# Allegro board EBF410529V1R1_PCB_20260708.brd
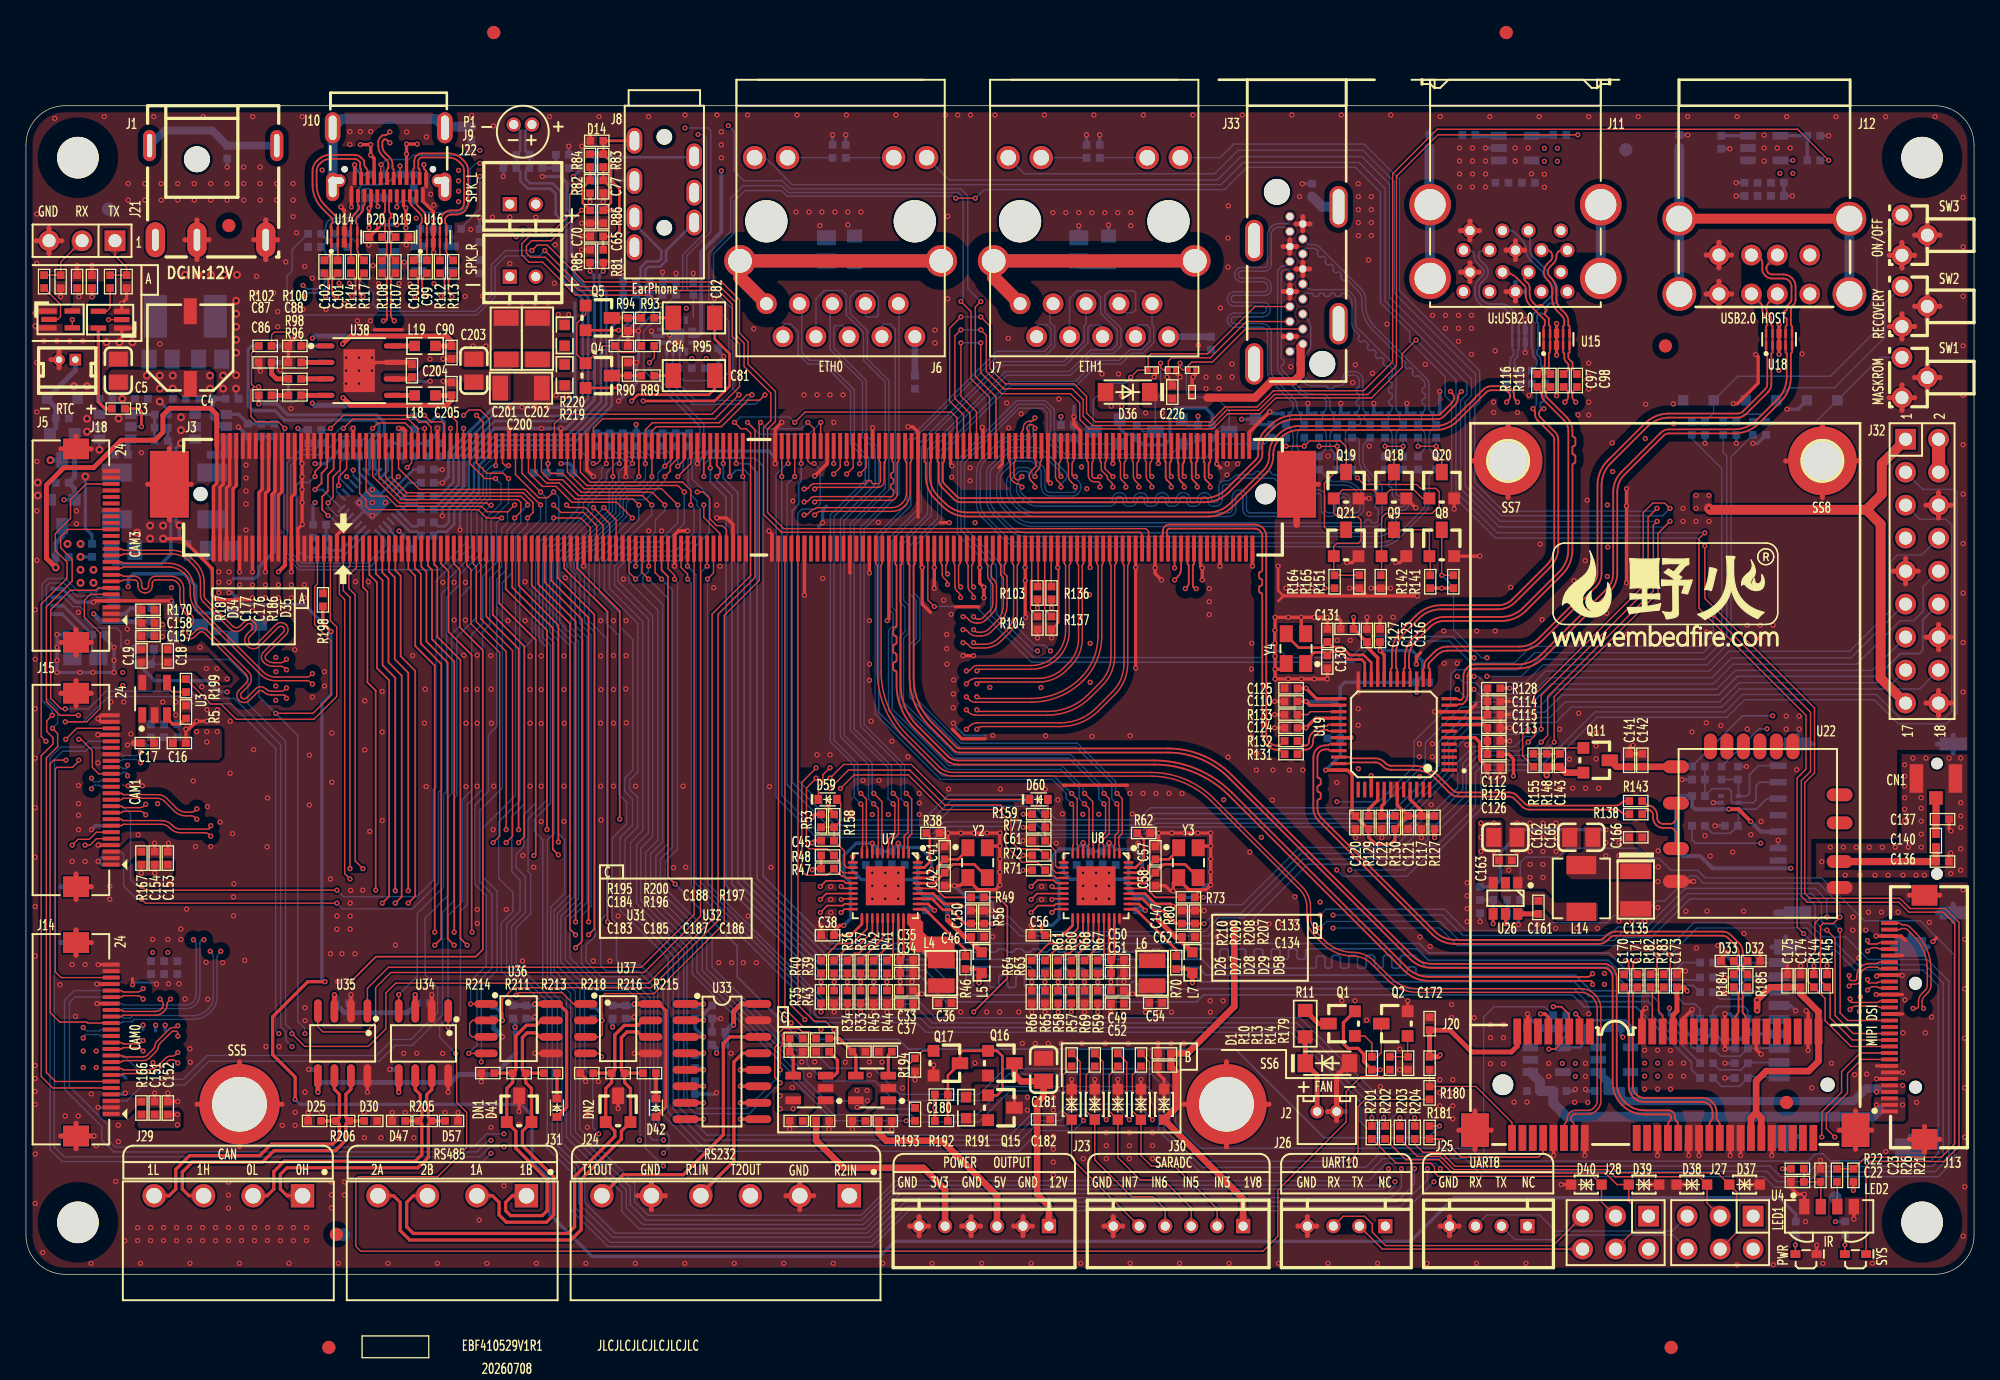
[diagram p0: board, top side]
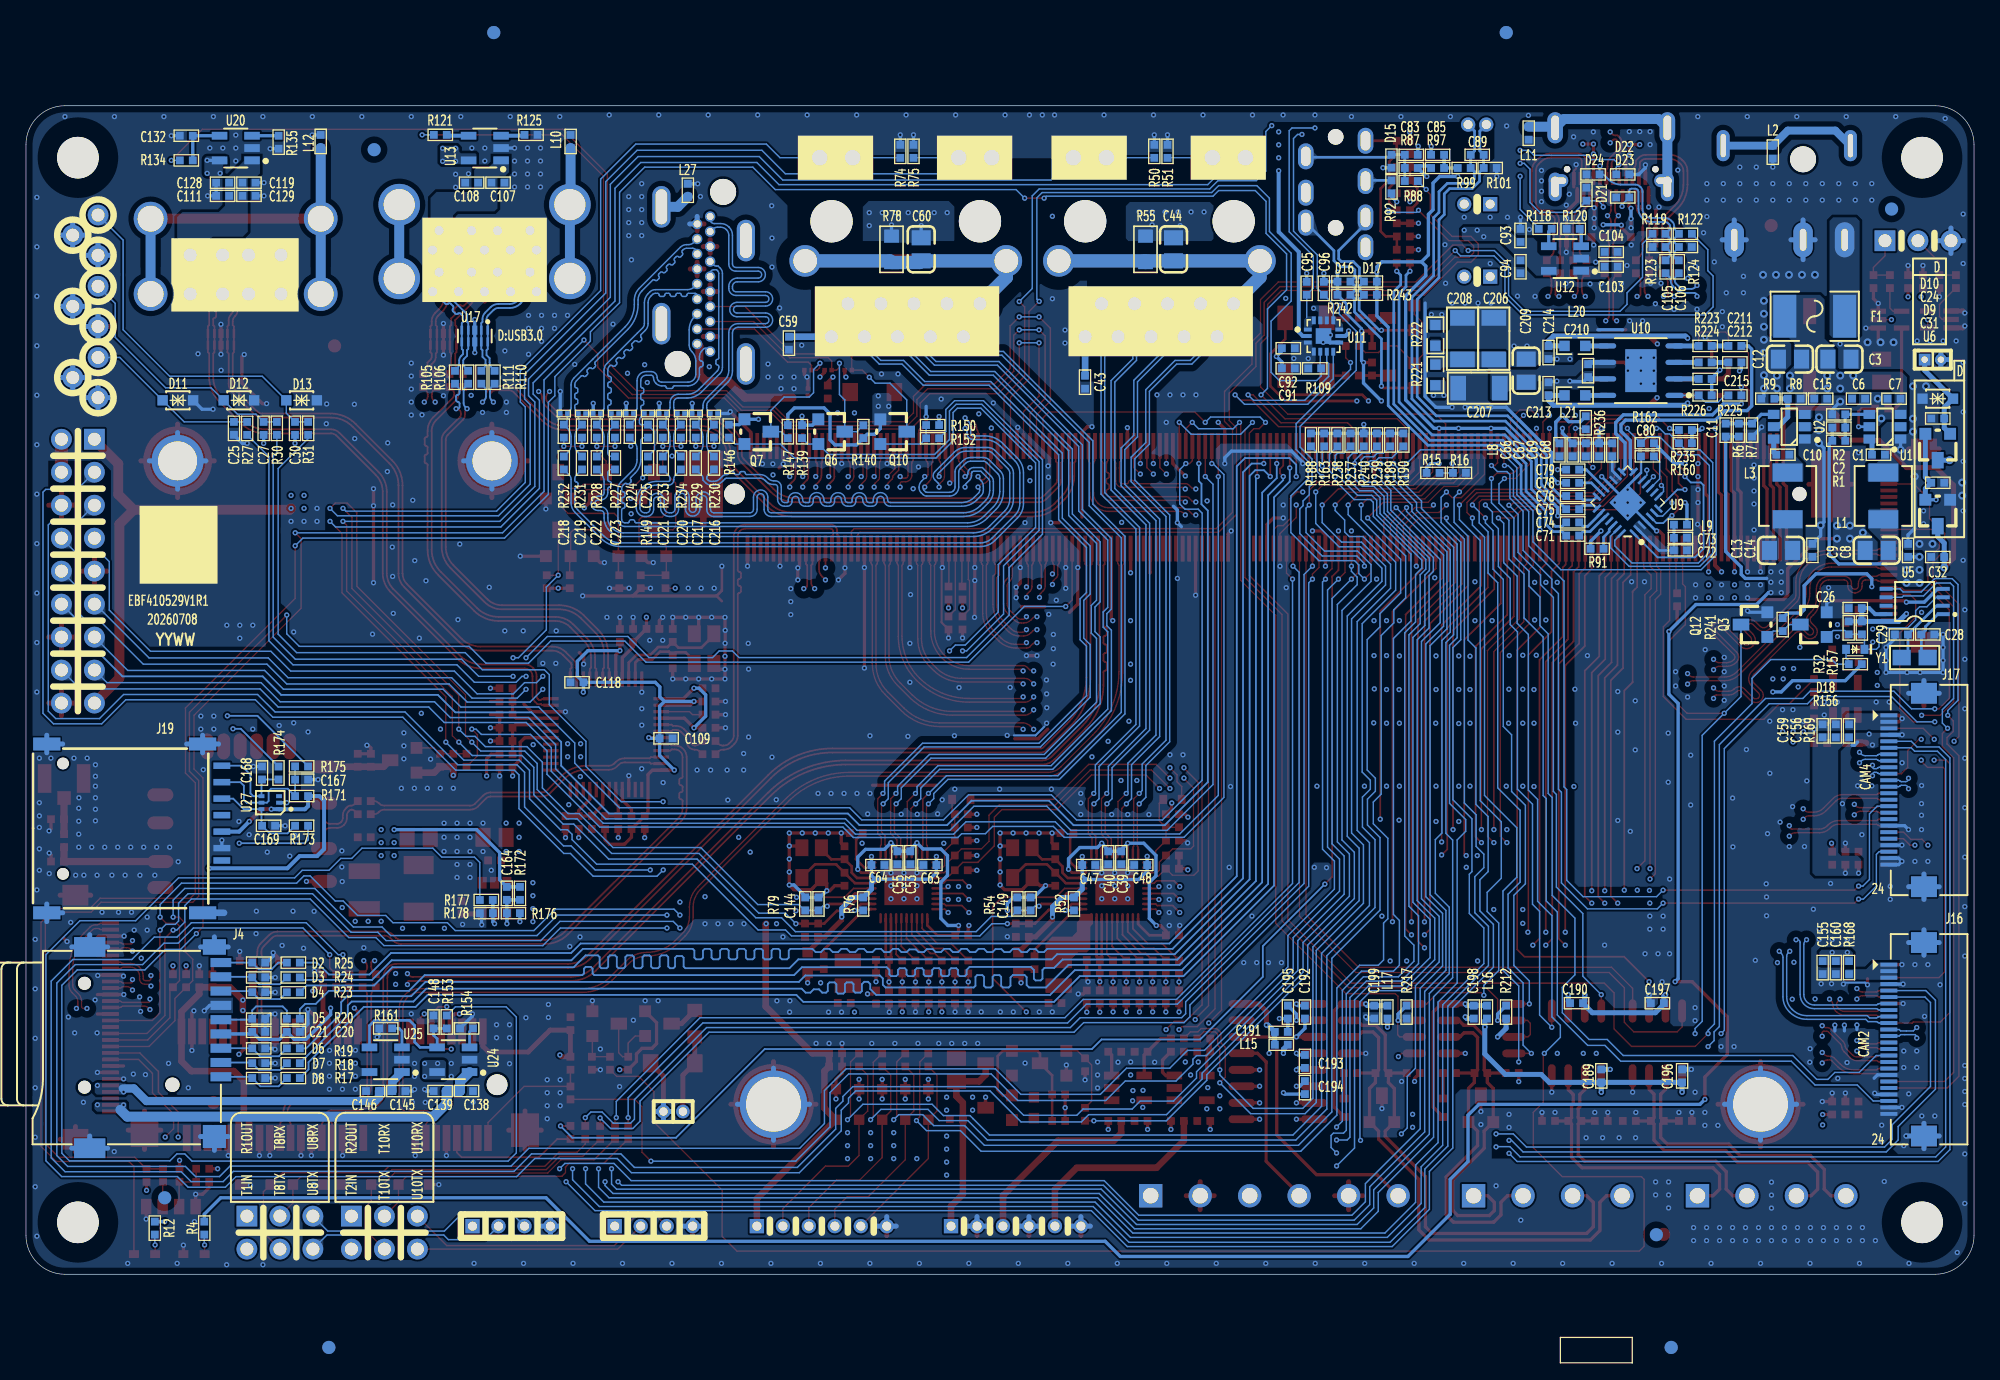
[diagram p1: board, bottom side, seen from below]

Outline 150 x 90 mm; copper layers: TOP, GND02, ART03, PWR04, GND05, BOTTOM. Coordinates in mm from the lower left corner of the outline.
Outline path: 0,87 arc(0.88,89.12) 3,90 147,90 arc(149.12,89.12) 150,87 150,3 arc(149.12,0.88) 147,0 3,0 arc(0.88,0.88) 0,3 0,87

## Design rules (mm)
constraint set DEFAULT: min track width 0.107
net group DIFFPAIR11: nets N17064495 N17064497
net group DIFFPAIR12: nets USB_HUB_DM3 USB_HUB_DP3
net group DIFFPAIR13: nets USB_HUB_DM4 USB_HUB_DP4
net group DIFFPAIR29: nets PCIE0_RXN PCIE0_RXP
net group DIFFPAIR30: nets PCIE0_REFCLKN PCIE0_REFCLKP
net group DP_TX_AUXN: nets DP_TX_AUXN SUB2
net group DP_TX_AUXP: nets DP_TX_AUXP SUB1
net group ETH0_MCLK_M0: nets ETH0_MCLK_M0 N16970797
net group ETH1_MCLK_M0: nets ETH1_MCLK_M0 N16976515
net group HDMI_TX_D0N: nets HDMI_TX_D0N HDMI_TX_D0N_PORT
net group HDMI_TX_D0P: nets HDMI_TX_D0P HDMI_TX_D0P_PORT
net group HDMI_TX_D1N: nets HDMI_TX_D1N HDMI_TX_D1N_PORT
net group HDMI_TX_D1P: nets HDMI_TX_D1P HDMI_TX_D1P_PORT
net group HDMI_TX_D2N: nets HDMI_TX_D2N HDMI_TX_D2N_PORT
net group HDMI_TX_D2P: nets HDMI_TX_D2P HDMI_TX_D2P_PORT
net group HDMI_TX_D3N: nets HDMI_TX_D3N HDMI_TX_D3N_PORT
net group HDMI_TX_D3P: nets HDMI_TX_D3P HDMI_TX_D3P_PORT
net group HDMI_TX_EARC+: nets HDMI_TX_EARC+ HDMI_TX_SBDP
net group HDMI_TX_EARC-: nets HDMI_TX_EARC- HDMI_TX_SBDN
net group MINIPCIE_NWDISABLE: nets MINIPCIE_NWDISABLE N17046548
net group PCIE0_CLKREQN_M0: nets N17044212 PCIE0_CLKREQN_M0
net group PCIE0_PERSTN: nets N17046561 PCIE0_PERSTN
net group PCIE0_TXN: nets PCIE0_TXN PE_TXN
net group PCIE0_TXP: nets PCIE0_TXP PE_TXP
net group PCIE0_WAKEN_M0: nets N17043933 PCIE0_WAKEN_M0
net group PWM0_CH0_M0_IR: nets N16966392 PWM0_CH0_M0_IR
net group SDMMC0_DETN: nets N16965221 SDMMC0_DETN
net group SIM_CLK0: nets N17036090 SIM_CLK0
net group SIM_DATA0: nets N17036093 SIM_DATA0
net group SIM_RST0: nets N17036087 SIM_RST0
net group TYPEC_SSRXN1: nets TYPEC_SSRXN1 USB3_OTG0_SSRX1N
net group TYPEC_SSRXN2: nets TYPEC_SSRXN2 USB3_OTG0_SSRX2N
net group TYPEC_SSRXP1: nets TYPEC_SSRXP1 USB3_OTG0_SSRX1P
net group TYPEC_SSRXP2: nets TYPEC_SSRXP2 USB3_OTG0_SSRX2P
net group TYPEC_SSTXN1: nets TYPEC_SSTXN1 USB3_OTG0_SSTX1N
net group TYPEC_SSTXN2: nets TYPEC_SSTXN2 USB3_OTG0_SSTX2N
net group TYPEC_SSTXP1: nets TYPEC_SSTXP1 USB3_OTG0_SSTX1P
net group TYPEC_SSTXP2: nets TYPEC_SSTXP2 USB3_OTG0_SSTX2P
net group USB2_OTG1_DM: nets N17161102 USB2_OTG1_DM
net group USB2_OTG1_DP: nets N17161099 USB2_OTG1_DP
net group USB20_DM2: nets USB20_DM2 USB_HUB_DM2
net group USB20_DP2: nets USB20_DP2 USB_HUB_DP2
net group USB30_DM: nets USB30_DM USB_HUB_DM1
net group USB30_DP: nets USB30_DP USB_HUB_DP1
net group USB30_RXN: nets USB3_OTG1_SSRXN USB30_RXN
net group USB30_RXP: nets USB3_OTG1_SSRXP USB30_RXP
net group USB30_TXN: nets USB3_OTG1_SSTXN USB30_TXN
net group USB30_TXP: nets USB3_OTG1_SSTXP USB30_TXP
net group USB_HUB_DM5: nets N17046088 USB_HUB_DM5
net group USB_HUB_DM6: nets N17367190 USB_HUB_DM6
net group USB_HUB_DP5: nets N17046085 USB_HUB_DP5
net group USB_HUB_DP6: nets N17367118 USB_HUB_DP6
net group 3W: nets CTP_RST LCD_BL_PWM LCD_RST
net group 50OHM: nets SAI1_LRCK_M0 SAI1_MCLK_M0 SAI1_SCLK_M0 SPI1_CLK_M0
net group C_GND_P: nets N16958730 N16985416 N17150434 N17163205 N17318769
net group PWR: nets 3V3_WLAN 12V_OUT RMII0_AVDD33 RMII1_AVDD33 RS485_1_3V3 RS485_2_3V3 SIM_VDD VCC3V3_RTC_S5 VCC_RTC
net group TYPEC_DM: nets USB2_OTG0_DM
net group TYPEC_DP: nets USB2_OTG0_DP

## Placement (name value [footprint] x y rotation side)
C1  0.1uF  [C0402]  7.36 63.12 180 bottom
C2  NC  [C0402]  10.41 65.21 0 bottom
C3  22uF  [C0805]  10.36 70.48 180 bottom
C4  100uF  [EC6P3]  12.65 71.37 180 top
C5  22uF  [C0805]  7.11 69.6 90 top
C6  0.1uF  [C0402]  8.89 67.44 180 bottom
C7  0.1uF  [C0402]  6.16 67.43 0 bottom
C8  0.1uF  [C0402]  5.08 55.75 90 bottom
C9  22uF  [C0805]  7.49 55.75 0 bottom
C10  0.1uF  [C0402]  14.72 63.12 180 bottom
C11  NC  [C0402]  19.12 65.02 270 bottom
C12  22uF  [C0805]  14.17 70.48 0 bottom
C13  22uF  [C0805]  14.86 55.75 0 bottom
C14  0.1uF  [C0402]  12.45 55.75 90 bottom
C15  0.1uF  [C0402]  11.81 67.44 180 bottom
C16  10uF  [C0402]  11.81 40.91 0 top
C17  0.1uF  [C0402]  9.35 40.91 180 top
C18  10uF  [C0402]  10.92 47.62 90 top
C19  0.1uF  [C0402]  8.89 47.62 90 top
C20  10uF  [C0402]  129.41 18.67 180 bottom
C21  0.1uF  [C0402]  132.08 18.67 180 bottom
C22  10uF  [C0402]  136.4 7.11 180 top
C23  0.1uF  [C0402]  138.18 7.62 90 top
C24  10uF  [C0402]  2.79 65.91 0 bottom
C25  NC  [C0402]  133.99 65.15 270 bottom
C26  0.1uF  [C0402]  9.14 51.31 0 bottom
C27  NC  [C0402]  131.7 65.15 270 bottom
C28  18pF  [C0402]  3.56 49.28 180 bottom
C29  18pF  [C0402]  5.59 49.28 0 bottom
C30  0.1uF  [C0402]  129.29 65.15 270 bottom
C31  1uF  [C0402]  2.79 60.96 180 bottom
C32  1uF  [C0402]  2.79 55.24 0 bottom
C33  10uF  [C0402]  67.82 21.86 0 top
C34  0.1uF  [C0402]  67.82 23.19 0 top
C35  0.1uF  [C0402]  67.82 24.21 0 top
C36  10uF  [C0402]  70.76 20.89 0 top
C37  0.1uF  [C0402]  67.82 20.85 180 top
C38  0.1uF  [C0402]  61.72 26.11 180 top
C39  0.1uF  [C0402]  65.67 32.08 270 bottom
C40  0.1uF  [C0402]  66.67 32.08 270 bottom
C41  18pF  [C0402]  70.74 32.46 90 top
C42  18pF  [C0402]  70.74 30.43 270 top
C43  0.1uF  [C0402]  68.45 68.71 270 bottom
C44  1nF  [C0805]  61.64 78.94 90 bottom
C45  0.1uF  [C0402]  61.72 33.4 180 top
C46  10uF  [C0402]  73.28 25.98 0 top
C47  0.1uF  [C0402]  68.17 31.52 180 bottom
C48  0.1uF  [C0402]  64.17 31.52 0 bottom
C49  10uF  [C0402]  84.05 21.86 0 top
C50  0.1uF  [C0402]  84.05 24.21 0 top
C51  0.1uF  [C0402]  84.05 23.19 0 top
C52  10uF  [C0402]  84.05 20.85 180 top
C53  0.1uF  [C0402]  81.91 32.08 270 bottom
C54  0.1uF  [C0402]  87 20.9 0 top
C55  0.1uF  [C0402]  82.9 32.08 270 bottom
C56  0.1uF  [C0402]  77.95 26.11 180 top
C57  18pF  [C0402]  86.97 32.46 90 top
C58  18pF  [C0402]  86.97 30.43 270 top
C59  0.1uF  [C0402]  91.25 71.71 270 bottom
C60  1nF  [C0805]  81.07 78.94 90 bottom
C61  0.1uF  [C0402]  77.98 33.4 180 top
C62  10uF  [C0402]  89.51 25.98 0 top
C63  0.1uF  [C0402]  80.4 31.52 0 bottom
C64  0.1uF  [C0402]  84.4 31.52 180 bottom
C65  270pF  [C0402]  43.94 79.93 180 top
C66  0.1uF  [C0402]  30.91 63.5 90 bottom
C67  0.1uF  [C0402]  29.89 63.5 90 bottom
C68  10uF  [C0402]  27.86 63.5 90 bottom
C69  10uF  [C0402]  28.87 63.5 90 bottom
C70  10uF  [C0402]  43.43 81.45 270 top
C71  1uF  [C0402]  30.91 56.89 0 bottom
C72  0.1uF  [C0402]  22.61 55.75 180 bottom
C73  10uF  [C0402]  22.61 56.72 180 bottom
C74  1uF  [C0402]  30.91 57.91 0 bottom
C75  1uF  [C0402]  30.91 58.93 0 bottom
C76  1uF  [C0402]  30.91 59.94 0 bottom
C77  NC  [C0402]  44.45 83.76 270 top
C78  10uF  [C0402]  30.91 60.96 0 bottom
C79  10uF  [C0402]  30.91 61.97 0 bottom
C80  10uF  [C0402]  25.15 62.99 0 bottom
C81  47uF  [C1206]  51.44 69.22 0 top
C82  47uF  [C1206]  51.44 73.66 0 top
C83  0.1uF  [C0402]  43.33 86.22 180 bottom
C84  0.1uF  [C0402]  45.85 71.5 0 top
C85  10uF  [C0402]  41.3 86.22 0 bottom
C86  0.1uF  [C0402]  18.41 67.69 0 top
C87  0.1uF  [C0402]  18.41 70.23 0 top
C88  1uF  [C0402]  20.7 70.23 180 top
C89  100pF  [C0402]  38.26 86.22 180 bottom
C90  1nF  [C0402]  32.77 70.99 270 top
C91  0.1uF  [C0402]  52.8 69.78 0 bottom
C92  10uF  [C0402]  52.8 71.32 0 bottom
C93  10uF  [C0402]  34.92 80.01 90 bottom
C94  0.1uF  [C0402]  34.92 77.6 270 bottom
C95  220pF  [C0402]  51.38 75.94 90 bottom
C96  220pF  [C0402]  50.06 75.94 90 bottom
C97  0.1uF  [C0402]  118.4 68.83 270 top
C98  0.1uF  [C0402]  119.42 68.83 270 top
C99  0.1uF  [C0402]  30.86 77.6 270 top
C100  0.1uF  [C0402]  29.84 77.6 270 top
C101  0.1uF  [C0402]  24 77.6 270 top
C102  0.1uF  [C0402]  22.99 77.6 270 top
C103  10uF  [C0402]  27.94 77.6 180 bottom
C104  0.1uF  [C0402]  27.94 78.74 180 bottom
C105  0.1uF  [C0402]  23.75 77.6 270 bottom
C106  0.1uF  [C0402]  22.73 77.6 270 bottom
C107  10uF  [C0402]  113.65 84.07 180 bottom
C108  0.1uF  [C0402]  115.68 84.07 0 bottom
C109  0.1uF  [C0402]  100.71 41.27 180 bottom
C110  0.1uF  [C0402]  97.41 44.12 180 top
C111  10uF  [C0402]  134.86 83.06 0 bottom
C112  NC  [C0402]  113.03 41.07 0 top
C113  NC  [C0402]  113.03 42.09 0 top
C114  NC  [C0402]  113.03 44.12 0 top
C115  NC  [C0402]  113.03 43.1 0 top
C116  0.1uF  [C0402]  104.27 49.2 90 top
C117  0.1uF  [C0402]  107.44 34.8 270 top
C118  0.1uF  [C0402]  107.57 45.59 0 bottom
C119  10uF  [C0402]  132.83 84.07 180 bottom
C120  0.1uF  [C0402]  102.36 34.8 270 top
C121  0.1uF  [C0402]  106.43 34.8 270 top
C122  0.1uF  [C0402]  104.39 34.8 270 top
C123  10uF  [C0402]  103.25 49.2 90 top
C124  0.1uF  [C0402]  97.41 42.09 180 top
C125  0.1uF  [C0402]  97.41 45.14 180 top
C126  0.1uF  [C0402]  113.03 39.04 0 top
C127  0.1uF  [C0402]  101.73 49.71 180 top
C128  10uF  [C0402]  134.86 84.07 0 bottom
C129  0.1uF  [C0402]  132.83 83.06 180 bottom
C130  NC  [C0402]  100.2 47.17 270 top
C131  NC  [C0402]  100.2 49.2 90 top
C132  0.1uF  [C0402]  137.65 87.69 0 bottom
C133  10uF  [C0402]  87.66 17.02 180 top
C134  0.1uF  [C0402]  87.66 16 180 top
C135  220uF  [CASE-B_3528]  123.95 29.59 270 top
C136  NC  [C0402]  147.57 31.79 0 top
C137  NC  [C0402]  147.57 35.05 0 top
C138  10uF  [C0402]  116.08 14.11 180 bottom
C139  0.1uF  [C0402]  118.11 14.11 0 bottom
C140  10pF  [C0402]  147.07 33.4 90 top
C141  10uF  [C0402]  123.44 39.59 90 top
C142  0.1uF  [C0402]  124.46 39.59 90 top
C143  0.1uF  [C0402]  118.11 39.59 90 top
C144  100pF  [C0402]  88.98 28.52 90 bottom
C145  10uF  [C0402]  121.28 14.11 180 bottom
C146  0.1uF  [C0402]  123.32 14.11 0 bottom
C147  100pF  [C0402]  89 27.51 90 top
C148  0.1uF  [C0402]  118.62 19.43 90 bottom
C149  100pF  [C0402]  72.64 28.52 90 bottom
C150  100pF  [C0402]  72.77 27.51 90 top
C151  10uF  [C0402]  9.91 12.8 90 top
C152  0.1uF  [C0402]  10.92 12.8 90 top
C153  10uF  [C0402]  10.92 32.05 90 top
C154  0.1uF  [C0402]  9.91 32.05 90 top
C155  10uF  [C0402]  11.66 23.62 270 bottom
C156  0.1uF  [C0402]  10.64 41.85 90 bottom
C157  10uF  [C0402]  9.4 49.15 180 top
C158  0.1uF  [C0402]  9.4 50.16 180 top
C159  10uF  [C0402]  11.66 41.85 90 bottom
C160  0.1uF  [C0402]  10.64 23.62 270 bottom
C161  0.1uF  [C0402]  116.46 28.26 90 top
C162  22uF  [C0805]  113.92 33.66 0 top
C163  0.1uF  [C0402]  113.92 31.88 0 top
C164  NC  [C0402]  112.98 29.34 90 bottom
C165  22uF  [C0805]  119.76 33.66 180 top
C166  0.1uF  [C0402]  123.95 33.66 0 top
C167  33pF  [C0402]  128.78 38.1 180 bottom
C168  33pF  [C0402]  131.83 38.61 90 bottom
C169  33pF  [C0402]  131.32 34.54 180 bottom
C170  0.1uF  [C0402]  123.06 22.61 270 top
C171  0.1uF  [C0402]  124.08 22.61 270 top
C172  0.1uF  [C0402]  108.08 19.3 90 top
C173  0.1uF  [C0402]  127.13 22.61 90 top
C174  0.1uF  [C0402]  136.65 22.61 90 top
C175  0.1uF  [C0402]  135.64 22.61 90 top
C176  0.1uF  [C0402]  5.08 76.45 90 top
C177  0.1uF  [C0402]  3.94 76.45 90 top
C180  0.1uF  [C0402]  70.48 13.84 0 top
C181  22uF  [C0805]  78.36 15.75 90 top
C182  0.1uF  [C0402]  78.36 11.94 0 top
C183  10uF  [C0402]  59.31 11.81 180 top
C184  0.1uF  [C0402]  59.31 17.14 0 top
C185  0.1uF  [C0402]  61.34 11.81 0 top
C186  10uF  [C0402]  66.17 11.81 0 top
C187  0.1uF  [C0402]  64.14 11.81 180 top
C188  0.1uF  [C0402]  64.14 17.14 0 top
C189  0.1uF  [C0402]  28.7 15.28 90 bottom
C190  0.1uF  [C0402]  30.61 20.88 0 bottom
C191  0.1uF  [C0402]  53.34 18.67 180 bottom
C192  0.1uF  [C0402]  51.52 20.19 90 bottom
C193  0.1uF  [C0402]  51.52 16.39 90 bottom
C194  0.1uF  [C0402]  51.52 14.38 270 bottom
C195  0.1uF  [C0402]  52.83 20.19 270 bottom
C196  0.1uF  [C0402]  22.48 15.28 90 bottom
C197  0.1uF  [C0402]  24.38 20.88 0 bottom
C198  0.1uF  [C0402]  38.52 20.19 270 bottom
C199  0.1uF  [C0402]  46.18 20.19 270 bottom
C200  47uF  [C1206]  38.12 68.25 0 top
C201  47uF  [C1206]  36.98 72.06 90 top
C202  47uF  [C1206]  39.39 72.06 90 top
C203  22uF  [C0805]  34.49 69.6 90 top
C204  0.1uF  [C0402]  29.72 69.6 90 top
C205  1nF  [C0402]  32.77 68.2 90 top
C206  47uF  [C1206]  36.98 72.06 90 bottom
C207  47uF  [C1206]  38.12 68.25 0 bottom
C208  47uF  [C1206]  39.39 72.06 90 bottom
C209  22uF  [C0805]  34.49 69.6 90 bottom
C210  0.1uF  [C0402]  29.72 69.6 270 bottom
C211  0.1uF  [C0402]  18.41 71.5 0 bottom
C212  0.1uF  [C0402]  18.41 70.23 0 bottom
C213  1nF  [C0402]  32.77 68.2 90 bottom
C214  1nF  [C0402]  32.77 70.99 270 bottom
C215  1uF  [C0402]  20.7 68.96 180 bottom
C216  0.22uF  [C0402]  97.03 62.48 90 bottom
C217  0.22uF  [C0402]  98.42 62.48 90 bottom
C218  0.22uF  [C0402]  108.58 62.48 90 bottom
C219  0.22uF  [C0402]  107.19 62.48 90 bottom
C220  0.22uF  [C0402]  99.57 62.48 90 bottom
C221  0.22uF  [C0402]  100.97 62.48 90 bottom
C222  0.22uF  [C0402]  106.05 62.48 90 bottom
C223  0.22uF  [C0402]  104.65 62.48 90 bottom
C224  1uF  [C0402]  103.5 64.94 90 bottom
C225  1uF  [C0402]  102.11 64.94 90 bottom
C226  1uF  [C0402]  88.27 67.94 90 top
CN1  WiFi-Ant  [UFL-3]  147.07 38.18 0 top
D1  1N4148W  [SOD-123]  100.2 16.26 180 top
D2  KLXES15AAA1  [ES0402]  132.08 24 0 bottom
D3  KLXES15AAA1  [ES0402]  132.08 22.86 0 bottom
D4  KLXES15AAA1  [ES0402]  132.08 21.72 0 bottom
D5  KLXES15AAA1  [ES0402]  132.08 19.68 0 bottom
D6  KLXES15AAA1  [ES0402]  132.08 17.4 0 bottom
D7  KLXES15AAA1  [ES0402]  132.08 16.26 0 bottom
D8  KLXES15AAA1  [ES0402]  132.08 15.11 0 bottom
D9  BAT54C  [SOT23]  2.79 63.74 0 bottom
D10  PESD3V3L1BA  [SOD323_T]  2.79 67.44 180 bottom
D11  PESD3V3L1BA  [SOD323_T]  138.3 67.31 0 bottom
D12  PESD3V3L1BA  [SOD323_T]  133.6 67.31 0 bottom
D13  PESD3V3L1BA  [SOD323_T]  128.78 67.31 0 bottom
D14  D2315-5R0B  [ESD0402]  43.95 87.3 0 top
D15  D2315-5R0B  [ESD0402]  44.86 85.72 90 bottom
D16  D2315-5R0B  [ESD0402]  48.51 76.45 180 bottom
D17  D2315-5R0B  [ESD0402]  46.48 76.45 0 bottom
D18  B5819WT  [SOD523]  9.14 48.13 0 bottom
D19  KLXES15AAA1  [ES0402]  28.96 79.88 180 top
D20  KLXES15AAA1  [ES0402]  26.92 79.88 0 top
D21  KLXES15AAA1  [ES0402]  29.84 83.19 270 bottom
D22  KLXES15AAA1  [ES0402]  27.05 84.71 0 bottom
D23  KLXES15AAA1  [ES0402]  27.05 82.93 180 bottom
D24  KLXES15AAA1  [ES0402]  29.34 84.71 180 bottom
D25  D2315-5R0B  [ESD0402]  22.23 11.81 180 top
D26  PESD3V3L1BA  [SOD323_T]  80.52 13.08 270 top
D27  PESD3V3L1BA  [SOD323_T]  82.3 13.08 270 top
D28  PESD3V3L1BA  [SOD323_T]  84.07 13.08 270 top
D29  PESD3V3L1BA  [SOD323_T]  85.85 13.08 270 top
D30  D2315-5R0B  [ESD0402]  26.54 11.81 0 top
D31  TPESD0201G05V  [R0201]  102.11 66.29 0 bottom
D32  KLXES15AAA1  [ES0402]  133.05 24.13 0 top
D33  KLXES15AAA1  [ES0402]  131.01 24.13 180 top
D34  D2315-3R3  [ESD0402]  2.67 76.45 90 top
D35  D2315-3R3  [ESD0402]  7.75 76.45 90 top
D36  1N5819W  [SOD-123]  84.84 67.94 0 top
D37  PESD3V3L1BA  [SOD323_T]  132.33 6.91 180 top
D38  PESD3V3L1BA  [SOD323_T]  128.27 6.91 0 top
D39  PESD3V3L1BA  [SOD323_T]  124.59 6.91 180 top
D40  PESD3V3L1BA  [SOD323_T]  120.14 6.91 0 top
D41  RB521S-30  [SOD523]  40.89 12.83 270 top
D42  RB521S-30  [SOD523]  48.51 12.83 270 top
D43  TPESD0201G05V  [R0201]  86.69 69.64 180 top
D44  TPESD0201G05V  [R0201]  103.5 66.29 180 bottom
D45  TPESD0201G05V  [R0201]  88.24 69.64 180 top
D46  TPESD0201G05V  [R0201]  89.79 69.64 180 top
D47  D2315-5R0B  [ESD0402]  28.7 11.81 180 top
D48  TPESD0201G05V  [R0201]  89.79 67.94 90 top
D49  TPESD0201G05V  [R0201]  99.57 66.29 0 bottom
D50  TPESD0201G05V  [R0201]  100.97 66.29 180 bottom
D51  TPESD0201G05V  [R0201]  106.05 66.29 180 bottom
D52  TPESD0201G05V  [R0201]  104.65 66.29 0 bottom
D53  TPESD0201G05V  [R0201]  97.03 66.29 0 bottom
D54  TPESD0201G05V  [R0201]  98.42 66.29 180 bottom
D55  TPESD0201G05V  [R0201]  108.58 66.29 180 bottom
D56  TPESD0201G05V  [R0201]  107.19 66.29 0 bottom
D57  D2315-5R0B  [ESD0402]  32.77 11.81 0 top
D58  PESD3V3L1BA  [SOD323_T]  87.63 13.08 270 top
D59  RB521S-30  [SOD523]  61.72 36.58 0 top
D60  RB521S-30  [SOD523]  77.98 36.58 0 top
DN1  SM712  [SOT23]  37.97 12.71 0 top
DN2  SM712  [SOT23]  45.59 12.71 0 top
F1  SMD1812P200TF16  [F1812]  12.27 73.79 0 bottom
J1  DC-044A-20A  [DC_IN_TH_3P_10R1X11R6]  14.41 84.18 270 top
J2  A1501WV-2P  [ZH1P5MM_TH_2P]  100.17 12.53 0 top
J3  -  [AS0B821-S55B-7H]  54.44 59.85 0 top
J4  TF_Card  [TFCARD]  145.49 18.41 270 bottom
J5  1.25T-2A  [GH1P25_TH_2P]  3.18 70.45 180 top
J6  -  [HY911130A]  62.73 81.1 0 top
J7  -  [HY911130A]  82.26 81.1 0 top
J8  PJ-393-7P  [AV7_6X14R50_TM]  49.15 84.1 0 top
J9  PH-2A  [PH-1X2-2P0_L]  38.26 82.42 0 top
J10  TYPE-C  [USB-C-SMD_TYC-324G]  27.93 85.68 180 top
J11  USB3D0_USB2D0-A-D  [USB3D0-AF-18P]  114.69 78.88 180 top
J12  -  [USB-A-D]  133.86 82 0 top
J13  FPC_0R5_30P_D  [FPC-30P-0P5]  144.84 19.8 90 top
J14  FPC_0P5_24P_D  [FPC_24P_0P5]  5.21 18.1 90 top
J15  FPC_0P5_24P_D  [FPC_24P_0P5]  5.21 37.3 90 top
J16  FPC_0P5_24P_D  [FPC_24P_0P5]  5.21 18.1 270 bottom
J17  FPC_0P5_24P_D  [FPC_24P_0P5]  5.21 37.3 270 bottom
J18  FPC_0P5_24P_D  [FPC_24P_0P5]  5.21 56.12 90 top
J19  SIM-7-1  [NANO_SIM]  141.66 34.34 270 bottom
J20  MINI-PCIE  [PCIE_52P]  126.22 14.6 0 top
J21  -  [HDR1X3-2R54-TM-VM]  4.32 79.6 180 top
J22  PH-2A  [PH-1X2-2P0_L]  38.26 76.84 0 top
J23  PH-6A  [PH-1X6-2P0]  73.77 3.71 180 top
J24  CON6  [DB2ERC-3P81-6P]  53.87 6.05 180 top
J25  PH-4A  [PH-1X4-2P0]  112.62 3.71 180 top
J26  PH-4A  [PH-1X4-2P0]  101.67 3.71 180 top
J27  -  [HDR2X3-2R54-TM-VM]  130.45 3.21 180 top
J28  -  [HDR2X3-2R54-TM-VM]  122.4 3.21 180 top
J29  WJ15EDGRC-3.81-4P  [DB2ERC-3P81-4P]  15.58 6.05 180 top
J30  PH-6A  [PH-1X6-2P0]  88.72 3.71 180 top
J31  WJ15EDGRC-3.81-4P  [DB2ERC-3P81-4P]  32.82 6.05 180 top
J32  -  [HDR2X9-2R54-TM-VM]  146 54.15 270 top
J33  HDMI-001C  [HDMI-SMD]  97.82 76.16 90 top
L1  3.3uH  [L4520]  6.99 59.95 270 bottom
L2  120R 100MHz  [L0402]  15.49 86.43 270 bottom
L3  3.3uH  [L4520]  14.35 59.95 270 bottom
L4  2.2uH  [L2520]  70.48 23.19 270 top
L5  330R 100MHz  [L0603]  73.58 24 90 top
L6  2.2uH  [L2520]  86.72 23.19 270 top
L7  330R 100MHz  [L0603]  89.81 24 90 top
L8  120R 100MHz  [L0402]  31.92 63.5 270 bottom
L9  120R 100MHz  [L0402]  22.61 57.73 0 bottom
L10  120R 100MHz  [L0402]  108.06 87.25 90 bottom
L11  120R 100MHz  [L0402]  34.29 87.88 270 bottom
L12  120R 100MHz  [L0402]  127.31 87.25 90 bottom
L14  3.3uH  [L4520]  119.76 29.72 90 top
L15  120R 100MHz  [L0402]  53.34 17.68 180 bottom
L16  120R 100MHz  [L0402]  37.5 20.19 90 bottom
L17  120R 100MHz  [L0402]  45.17 20.19 90 bottom
L18  1K 100MHz  [L0603]  30.73 67.69 0 top
L19  1K 100MHz  [L0603]  30.73 71.5 0 top
L20  1K 100MHz  [L0603]  30.73 71.5 0 bottom
L21  1K 100MHz  [L0603]  30.73 67.69 0 bottom
L27  120R 100MHz  [L0402]  99.03 83.49 270 bottom
LED1  HS-0602-UR  [LED_HS_0602_UR]  137.06 1.56 180 top
LED2  HS-0602-UG  [LED_HS_0602_UR]  140.87 1.56 180 top
NOREF  -  []  152.54 0 0 top
NOREF#2  -  [unnamed#2]  15.62 80.77 0 top
NOREF#3  -  []  9.4 -7.62 0 top
NOREF#4  -  [unnamed#2]  135.56 13.23 0 top
NOREF#5  -  [unnamed#2]  23.9 3.07 0 top
NOREF#6  -  [unnamed#2]  126.68 -5.63 180 top
NOREF#7  -  []  154.05 56.9 0 top
NOREF#8  -  []  152.54 90 0 top
NOREF#9  -  []  208.79 7.87 0 top
NOREF#10  -  [unnamed#2]  113.98 95.64 180 top
NOREF#11  -  [unnamed#2]  36.02 95.64 0 top
NOREF#12  -  [unnamed#2]  126.24 71.5 0 top
NOREF#13  -  []  0 87 0 top
NOREF#14  -  [unnamed#2]  23.32 -5.63 0 top
NOREF#15  -  []  3 0 90 top
NOREF#16  -  [unnamed#2]  24.46 3.05 180 bottom
NOREF#17  -  [unnamed#2]  23.32 -5.63 180 bottom
NOREF#18  -  [unnamed#2]  123.19 86.61 180 bottom
NOREF#19  -  [unnamed#2]  6.35 82.04 180 bottom
NOREF#20  -  [unnamed#2]  126.68 -5.63 180 bottom
NOREF#21  -  [unnamed#2]  36.02 95.64 180 bottom
NOREF#22  -  [unnamed#2]  113.98 95.64 180 bottom
NOREF#23  -  [unnamed#2]  139.32 5.89 180 bottom
P1  MIC_POM  [MIC2-4R00-TM]  38.26 88.55 180 top
Q1  SSM3J328R-LF  [SOT23]  101.33 19.3 90 top
Q2  SS8050  [SOT23]  105.4 19.3 90 top
Q3  2SK3018  [SOT23]  12.33 50.04 90 bottom
Q4  WNM2016-3/TR  [SOT23]  44.08 69.22 270 top
Q5  WNM2016-3/TR  [SOT23]  44.08 73.66 270 top
Q6  2SK3018  [SOT23]  88 64.9 270 bottom
Q7  2SK3018  [SOT23]  93.69 64.9 270 bottom
Q8  2SK3018  [SOT23]  109.02 56.3 0 top
Q9  2SK3018  [SOT23]  105.33 56.3 0 top
Q10  2SK3018  [SOT23]  83.22 64.9 270 bottom
Q11  AO3407  [SOT23]  120.92 39.59 270 top
Q12  2SK3018  [SOT23]  16.9 50.04 90 bottom
Q15  AO3407  [SOT23]  75.07 12.83 270 top
Q16  AO3407  [SOT23]  75.07 16.26 270 top
Q17  SS8050  [SOT23]  70.88 16.26 270 top
Q18  2SK3018  [SOT23]  105.33 60.74 0 top
Q19  2SK3018  [SOT23]  101.65 60.74 0 top
Q20  2SK3018  [SOT23]  109.02 60.74 0 top
Q21  2SK3018  [SOT23]  101.65 56.3 0 top
R1  115K  [R0402]  10.41 64.2 0 bottom
R2  20K  [R0402]  10.41 66.23 0 bottom
R3  10K  [R0402]  7.11 66.67 0 top
R4  5.1K  [R0402]  136.27 3.56 270 bottom
R5  3.4K  [R0402]  12.32 43.31 90 top
R6  115K  [R0402]  18.11 65.02 270 bottom
R7  20K  [R0402]  17.09 65.02 270 bottom
R8  180K  [R0402]  13.84 67.44 180 bottom
R9  27K  [R0402]  15.88 67.44 0 bottom
R10  10K  [R0402]  103.63 16.26 90 top
R11  0R  [R0805]  98.5 19.3 270 top
R12  4.7K  [R0402]  140.08 3.56 270 bottom
R13  1K  [R0402]  105.03 16.26 90 top
R14  10K  [R0402]  106.43 16.26 270 top
R15  25.5K  [R0402]  41.66 61.72 180 bottom
R16  10K  [R0402]  39.62 61.72 180 bottom
R17  22R  [R0402]  129.41 15.11 0 bottom
R18  22R  [R0402]  129.41 16.26 0 bottom
R19  22R  [R0402]  129.41 17.4 0 bottom
R20  22R  [R0402]  129.41 19.68 0 bottom
R21  10K  [R0402]  140.72 7.62 90 top
R22  22R  [R0402]  136.4 8.13 0 top
R23  22R  [R0402]  129.41 21.72 0 bottom
R24  22R  [R0402]  129.41 22.86 0 bottom
R25  22R  [R0402]  129.41 24 0 bottom
R26  22R  [R0402]  139.45 7.62 270 top
R27  100R  [R0402]  132.97 65.15 270 bottom
R30  100R  [R0402]  130.68 65.15 270 bottom
R31  100R  [R0402]  128.27 65.15 270 bottom
R32  NC  [R0402]  9.65 49.78 270 bottom
R33  4.7K  [R0402]  64.26 21.36 90 top
R34  4.7K  [R0402]  63.25 21.36 90 top
R35  4.7K  [R0402]  61.21 21.36 90 top
R36  22R  [R0402]  63.25 23.67 90 top
R37  22R  [R0402]  64.26 23.67 90 top
R38  2.49K  [R0402]  69.84 33.99 0 top
R39  22R  [R0402]  62.23 23.67 90 top
R40  22R  [R0402]  61.21 23.67 90 top
R41  22R  [R0402]  66.29 23.67 90 top
R42  22R  [R0402]  65.28 23.67 90 top
R43  4.7K  [R0402]  62.23 21.36 270 top
R44  4.7K  [R0402]  66.29 21.36 270 top
R45  4.7K  [R0402]  65.28 21.36 270 top
R46  4.7K  [R0402]  72.34 24 90 top
R47  4.7K  [R0402]  61.72 31.24 0 top
R48  4.7K  [R0402]  61.72 32.26 0 top
R49  22R  [R0402]  73.28 29.03 180 top
R50  510R  [R0402]  63.12 86.49 90 bottom
R51  510R  [R0402]  62.1 86.49 90 bottom
R52  4.7K  [R0402]  69.3 28.52 90 bottom
R53  10K  [R0402]  61.21 34.92 270 top
R54  4.7K  [R0402]  73.66 28.52 90 bottom
R55  1M  [R0805]  63.8 78.94 90 bottom
R56  4.7K  [R0402]  73.79 27.51 90 top
R57  4.7K  [R0402]  80.49 21.36 90 top
R58  4.7K  [R0402]  79.48 21.36 90 top
R59  4.7K  [R0402]  82.52 21.36 90 top
R60  22R  [R0402]  80.49 23.67 90 top
R61  22R  [R0402]  79.48 23.67 90 top
R62  2.49K  [R0402]  86.07 33.99 0 top
R63  22R  [R0402]  78.46 23.67 90 top
R64  22R  [R0402]  77.44 23.67 90 top
R65  4.7K  [R0402]  78.46 21.36 270 top
R66  4.7K  [R0402]  77.44 21.36 270 top
R67  22R  [R0402]  82.52 23.67 90 top
R68  22R  [R0402]  81.51 23.67 90 top
R69  4.7K  [R0402]  81.51 21.36 270 top
R70  4.7K  [R0402]  88.57 24 90 top
R71  4.7K  [R0402]  77.98 31.11 0 top
R72  4.7K  [R0402]  77.98 32.26 0 top
R73  22R  [R0402]  89.51 29.03 180 top
R74  510R  [R0402]  82.68 86.49 90 bottom
R75  510R  [R0402]  81.66 86.49 90 bottom
R76  4.7K  [R0402]  85.53 28.52 90 bottom
R77  10K  [R0402]  77.98 34.42 0 top
R78  1M  [R0805]  83.35 78.94 90 bottom
R79  4.7K  [R0402]  89.99 28.52 90 bottom
R80  4.7K  [R0402]  90.02 27.51 90 top
R81  0R  [R0402]  44.45 78.41 270 top
R82  100R  [R0402]  43.43 83.76 270 top
R83  100K  [R0402]  44.45 85.78 270 top
R84  2.2K  [R0402]  43.43 85.78 90 top
R85  0R  [R0402]  43.43 78.41 270 top
R86  100K  [R0402]  44.45 81.45 270 top
R87  100K  [R0402]  43.33 85.21 0 bottom
R88  0R  [R0402]  43.33 84.2 180 bottom
R89  0R  [R0402]  47.88 69.22 0 top
R90  470R  [R0402]  46.35 69.72 90 top
R91  10K  [R0402]  29.03 55.88 180 bottom
R92  0R  [R0402]  44.86 83.75 270 bottom
R93  0R  [R0402]  47.88 73.66 0 top
R94  470R  [R0402]  46.35 73.15 270 top
R95  300K  [R0402]  47.88 71.5 0 top
R96  20K  [R0402]  20.7 67.69 0 top
R97  100R  [R0402]  41.3 85.21 0 bottom
R98  20K  [R0402]  20.7 68.96 0 top
R99  1K  [R0402]  39.26 85.21 180 bottom
R100  10K  [R0402]  20.7 71.5 180 top
R101  1K  [R0402]  37.26 85.21 180 bottom
R102  1K  [R0402]  18.41 71.5 0 top
R103  4.7K  [R0402]  77.89 52.48 90 top
R104  NC  [R0402]  77.89 50.17 90 top
R105  0R  [R0402]  116.97 69.09 270 bottom
R106  0R  [R0402]  115.95 69.09 270 bottom
R107  0R  [R0402]  28.45 77.6 270 top
R108  0R  [R0402]  27.43 77.6 270 top
R109  10K  [R0402]  50.77 69.78 180 bottom
R110  0R  [R0402]  113.92 69.09 270 bottom
R111  0R  [R0402]  114.94 69.09 270 bottom
R112  0R  [R0402]  31.88 77.6 270 top
R113  0R  [R0402]  32.89 77.6 270 top
R114  0R  [R0402]  25.02 77.6 270 top
R115  0R  [R0402]  117.39 68.83 270 top
R116  0R  [R0402]  116.37 68.83 270 top
R117  0R  [R0402]  26.04 77.6 270 top
R118  10K  [R0402]  33.02 80.52 180 bottom
R119  100K  [R0402]  24.26 80.14 0 bottom
R120  3.4K  [R0402]  30.86 80.52 0 bottom
R121  10K  [R0402]  118.1 87.76 180 bottom
R122  100K  [R0402]  22.23 80.14 180 bottom
R123  NC  [R0402]  24.26 79.12 0 bottom
R124  NC  [R0402]  22.23 79.12 180 bottom
R125  3.4K  [R0402]  111.11 87.76 180 bottom
R126  NC  [R0402]  113.03 40.06 180 top
R127  0R  [R0402]  108.46 34.8 90 top
R128  NC  [R0402]  113.03 45.14 0 top
R129  100K  [R0402]  103.38 34.8 270 top
R130  10K  [R0402]  105.41 34.8 270 top
R131  0R  [R0402]  97.41 40.06 0 top
R132  0R  [R0402]  97.41 41.07 0 top
R133  2.7K  [R0402]  97.41 43.1 180 top
R134  10K  [R0402]  137.65 85.79 180 bottom
R135  3.4K  [R0402]  130.54 87.19 270 bottom
R136  4.7K  [R0402]  78.96 52.48 90 top
R137  NC  [R0402]  78.96 50.17 90 top
R138  0R  [R0402]  123.95 35.43 0 top
R139  10K  [R0402]  90.25 64.9 270 bottom
R140  1.8K  [R0402]  85.52 64.9 90 bottom
R141  47K  [R0402]  109.91 53.34 90 top
R142  47K  [R0402]  108.13 53.34 90 top
R143  0R  [R0402]  123.95 36.45 0 top
R144  NC  [R0402]  137.67 22.61 270 top
R145  NC  [R0402]  138.68 22.61 270 top
R146  10K  [R0402]  95.89 64.94 270 bottom
R147  1.8K  [R0402]  91.34 64.9 270 bottom
R148  10K  [R0402]  117.09 39.59 90 top
R149  1.2K  [R0402]  102.11 62.48 90 bottom
R150  27K  [R0402]  80.19 65.41 0 bottom
R151  47K  [R0402]  104.32 53.34 270 top
R152  100R  [R0402]  80.19 64.39 0 bottom
R153  1K  [R0402]  117.6 19.43 270 bottom
R154  3.4K  [R0402]  116.08 18.94 0 bottom
R155  1K  [R0402]  116.08 39.59 90 top
R156  10K  [R0402]  9.14 46.99 0 bottom
R157  10K  [R0402]  8.64 49.78 270 bottom
R158  NC  [R0402]  62.23 34.92 270 top
R159  NC  [R0402]  77.98 35.43 0 top
R160  2.2K  [R0402]  22.23 64.01 0 bottom
R161  3.4K  [R0402]  122.3 18.94 0 bottom
R162  2.2K  [R0402]  25.15 64.01 0 bottom
R163  2.2K  [R0402]  50.04 64.26 270 bottom
R164  1K  [R0402]  100.76 53.34 90 top
R165  10K  [R0402]  102.67 53.34 270 top
R166  0R  [R0402]  8.89 12.8 90 top
R167  0R  [R0402]  8.89 32.05 90 top
R168  0R  [R0402]  9.62 23.62 270 bottom
R169  0R  [R0402]  9.62 41.85 90 bottom
R170  0R  [R0402]  9.4 51.18 180 top
R171  15K  [R0402]  128.78 36.83 0 bottom
R172  100K  [R0402]  111.96 29.34 90 bottom
R173  0R  [R0402]  128.78 34.54 0 bottom
R174  0R  [R0402]  130.56 38.61 270 bottom
R175  0R  [R0402]  128.78 39.12 0 bottom
R176  30K  [R0402]  112.47 27.81 180 bottom
R177  1K  [R0402]  114.55 28.83 180 bottom
R178  10K  [R0402]  114.55 27.81 0 bottom
R179  4.7K  [R0402]  108.08 16.26 270 top
R180  22R  [R0402]  108.08 13.97 90 top
R181  22R  [R0402]  108.08 10.92 270 top
R182  100R  [R0402]  125.09 22.61 90 top
R183  100R  [R0402]  126.11 22.61 90 top
R184  2.2R  [R0402]  131.51 22.61 90 top
R185  2.2R  [R0402]  132.55 22.61 90 top
R186  100R  [R0402]  6.48 76.45 270 top
R187  100R  [R0402]  1.4 76.45 270 top
R188  2.2K  [R0402]  51.05 64.26 270 bottom
R189  2.2K  [R0402]  44.96 64.26 270 bottom
R190  2.2K  [R0402]  43.94 64.26 270 bottom
R191  0R  [R0603]  72.39 12.83 90 top
R192  20K  [R0402]  70.48 11.81 0 top
R193  1K  [R0402]  68.45 12.32 90 top
R194  10K  [R0402]  68.45 16.13 270 top
R195  1K  [R0402]  59.31 18.16 180 top
R196  3.4K  [R0402]  61.34 17.14 180 top
R197  3.4K  [R0402]  66.17 17.14 180 top
R198  0R  [R0402]  22.86 51.94 270 top
R199  1K  [R0402]  12.32 45.34 270 top
R200  1K  [R0402]  61.34 18.16 0 top
R201  100R  [R0402]  103.63 10.92 270 top
R202  100R  [R0402]  104.65 10.92 270 top
R203  100R  [R0402]  105.79 10.92 270 top
R204  100R  [R0402]  106.93 10.92 270 top
R205  120R  [R0402]  30.73 11.81 180 top
R206  120R  [R0402]  24.38 11.81 180 top
R207  100R  [R0402]  85.85 16.51 270 top
R208  100R  [R0402]  84.07 16.51 270 top
R209  100R  [R0402]  82.3 16.51 270 top
R210  100R  [R0402]  80.52 16.51 270 top
R211  120R  [R0402]  37.97 15.49 0 top
R212  10K  [R0402]  36.03 20.19 270 bottom
R213  4.7K  [R0402]  40.39 15.49 0 top
R214  4.7K  [R0402]  35.56 15.49 180 top
R215  4.7K  [R0402]  48.01 15.49 0 top
R216  120R  [R0402]  45.59 15.49 0 top
R217  10K  [R0402]  43.69 20.19 270 bottom
R218  4.7K  [R0402]  43.18 15.49 180 top
R219  0R  [R0603]  41.48 69.27 90 top
R220  NC  [R0603]  41.48 72.31 270 top
R221  0R  [R0603]  41.48 69.27 90 bottom
R222  NC  [R0603]  41.48 72.31 270 bottom
R223  20K  [R0402]  20.7 71.5 0 bottom
R224  20K  [R0402]  20.7 70.23 0 bottom
R225  1K  [R0402]  18.41 67.69 0 bottom
R226  10K  [R0402]  20.7 67.69 180 bottom
R227  499R  [R0402]  104.65 64.94 270 bottom
R228  499R  [R0402]  106.05 64.94 270 bottom
R229  499R  [R0402]  98.42 64.94 270 bottom
R230  499R  [R0402]  97.03 64.94 270 bottom
R231  499R  [R0402]  107.19 64.94 270 bottom
R232  499R  [R0402]  108.58 64.94 270 bottom
R233  499R  [R0402]  100.97 64.94 270 bottom
R234  499R  [R0402]  99.57 64.94 270 bottom
R235  2.2K  [R0402]  22.23 65.02 0 bottom
R236  2.2K  [R0402]  29.9 65.58 270 bottom
R237  2.2K  [R0402]  48.01 64.26 270 bottom
R238  2.2K  [R0402]  49.02 64.26 270 bottom
R239  2.2K  [R0402]  45.97 64.26 270 bottom
R240  2.2K  [R0402]  46.99 64.26 270 bottom
R241  10K  [R0402]  14.73 50.04 270 bottom
R242  470R  [R0402]  48.51 75.44 0 bottom
R243  470R  [R0402]  46.48 75.44 180 bottom
SS1  -  [NPTH_M3]  4 86 0 top
SS2  -  [NPTH_M3]  4 4 0 top
SS3  -  [NPTH_M3]  146 86 0 top
SS4  -  [NPTH_M3]  146 4 0 top
SS5  M2.5X3mm  [SMTSO-M2R5]  16.44 13.09 0 top
SS6  M2.5X3mm  [SMTSO-M2R5]  92.44 13.09 0 top
SS7  M2X4mm  [SMTWE_M2]  114.12 62.65 180 top
SS8  M2X4mm  [SMTWE_M2]  138.32 62.65 180 top
SW1  TS-1091B-A7B3-D2  [SW_TH3_4P5X4P5X6P5]  145.42 69.06 90 top
SW2  TS-1091B-A7B3-D2  [SW_TH3_4P5X4P5X6P5]  145.42 74.55 90 top
SW3  TS-1091B-A7B3-D2  [SW_TH3_4P5X4P5X6P5]  145.42 80.03 90 top
U1  ASP9135ZC-R  [SOT23_6]  6.86 65.28 90 bottom
U2  ASP9135ZC-R  [SOT23_6]  14.22 65.28 90 bottom
U3  LPW5209AB5F  [SOT23-5]  9.91 44.32 0 top
U4  NC  [SMD4-6R80X2R50]  138.84 5.21 180 top
U5  BM8563EMA  [MSOP-8]  4.57 51.82 90 bottom
U6  XC6206P332MR  [SOT-23-3]  2.79 58.66 0 bottom
U7  RTL8211F  [QFP_40P_R]  66.17 29.92 270 top
U8  RTL8211F  [QFP_40P_R]  82.4 29.92 270 top
U9  ES8388  [QFN28_0R45-4X4EP2R6X2R6]  26.67 59.43 45 bottom
U10  NS4110B  [SOP-8-EP-2R5X3R4]  25.65 69.6 90 bottom
U11  FUSB302BMPX  [WQFN14-0R50-2R5X2R5EP1R45X1R45]  50.09 72.26 180 bottom
U12  LPW5209AB5F  [SOT23-5]  31.5 78.23 90 bottom
U13  LPW5209AB5F  [SOT23-5]  114.67 86.74 90 bottom
U14  RCLAMP0524P  [USON_10]  24.51 79.88 0 top
U15  RCLAMP0524P  [USON_10]  117.86 72.01 0 top
U16  RCLAMP0524P  [USON_10]  31.37 79.88 0 top
U17  RCLAMP0524P  [USON_10]  115.44 72.26 0 bottom
U18  RCLAMP0524P  [USON_10]  134.99 72.01 0 top
U19  FE2.1-CQFP48A  [LQFP48_0P5_7X7]  105.33 41.58 180 top
U20  LPW5209AB5F  [SOT23-5]  133.84 86.74 90 bottom
U22  TL8821CUB  [RL-UM02WBS-8723BU]  133.35 33.76 180 top
U24  LPW5209AB5F  [SOT23-5]  117.09 16.53 90 bottom
U25  LPW5209AB5F  [SOT23-5]  122.3 16.53 90 bottom
U26  ASP9135ZC-R  [SOT23_6]  113.92 28.96 180 top
U27  NUP5120X6T1G  [SOT563]  131.19 36.32 90 bottom
U28  74LVC1G125GW  [SOT-353]  6.48 73.52 90 top
U29  74LVC1G125GW  [SOT-353]  2.67 73.54 270 top
U31  LPW5209AB5F  [SOT23-5]  60.33 14.35 90 top
U32  LPW5209AB5F  [SOT23-5]  65.15 14.35 90 top
U33  SIT3232EESE  [SOIC16]  53.59 16.38 0 top
U34  SIT1042AQT/3  [SOP8]  30.61 17.78 180 top
U35  SIT1042AQT/3  [SOP8]  24.38 17.78 180 top
U36  SIT3088EESA  [SOP8]  37.93 18.92 270 top
U37  SIT3088EESA  [SOP8]  45.59 18.92 270 top
U38  NS4110B  [SOP-8-EP-2R5X3R4]  25.65 69.6 270 top
Y1  32.768KHz  [3215]  4.57 47.5 0 bottom
Y2  25MHz  [3225]  73.28 31.7 270 top
Y3  25MHz  [3225]  89.51 31.7 270 top
Y4  12MHz  [3225]  97.79 48.18 90 top

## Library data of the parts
C1-C3 C5-C96 C103 C104 C107-C134 C136-C169 C172-C177 C180-C215 C226 = CAP_NP
C4 C135 = CAP
C97-C102 C105 C106 C170 C171 = CAP_NP: signal model: CAP_NP_C0402_DISCRETE_0.1UF_0.1uF
C216-C223 = CAP_NP: signal model: CAP_NP_C0402_DISCRETE_0.22UF_0.22uF
C224 C225 = CAP_NP: signal model: CAP_NP_C0402_DISCRETE_1UF_1uF
CN1 = WIFI_ANT
D1 = DIODE
D2-D8 D10-D17 D19-D35 D37-D40 D44 D47 D57 D58 = DIODE BI-DIR TRIG
D9 = BAT54C
D18 D36 D41 D42 D59 D60 = DIODE_SCHTKY
D43 D45 D46 D48 D51 D52 D55 D56 = DIODE BI-DIR TRIG: signal model: DIODE_BI-DIR_TRIG_R0201_D1250-5R5C_D1250-5R5C
D49 D50 D53 D54 = DIODE BI-DIR TRIG: signal model: DIODE_BI-DIR_TRIG_R0201_TPESD0201G05V_TPESD0201G05V
DN1 DN2 = TVS Arr ComA
F1 = FUSE
J1 = DC-044A-20A
J2 J5 J9 J22 = 1X2PIN
J3 = AS0B821-S55B-7H
J4 = TF_Card
J6 J7 = HY911130A
J8 = PJ-393
J10 = TYPE-C-24P
J11 = USB3D0_USB2D0-A-D
J12 = USB-A-D
J13 = FPC-30P
J14-J18 = FPC-24P
J19 = SIM-7-1
J20 = MINI-PCIE
J21 = 1X3PIN
J23 J30 = 1X6PIN
J24 = CON6
J25 J26 = 1X4PIN
J27 J28 = 2X3PIN
J29 J31 = CON4
J32 = 2X9PIN
J33 = HDMI-001C
L1 L3 L4 L6 L14 = IND
L2 L5 L7-L12 L15-L21 L27 = BEAD
LED1 LED2 = LED
P1 = MIC_POM
Q1 Q11 Q15 Q16 = MOSFET_P
Q2 Q17 = NPN
Q3 Q6-Q10 Q12 Q18-Q21 = 2SK3018
Q4 Q5 = MOSFET N
R1-R16 R21 R27 R30-R35 R38 R43-R48 R50-R59 R62 R65 R66 R69-R72 R74-R104 R109 R118-R130 R133-R137 R139-R142 R144-R172 R176-R179 R186-R243 = RES
R17-R20 R22-R26 R36 R37 R39-R42 R49 R60 R61 R63 R64 R67 R68 R73 R180 R181 = RES: signal model: RES_R0402_DISCRETE_22R_22R
R105-R108 R110-R117 R131 R132 R138 R143 R173-R175 = RES: signal model: RES_R0402_DISCRETE_0R_0R
R182 R183 = RES: signal model: RES_R0402_DISCRETE_100R_100R
R184 R185 = RES: signal model: RES_R0402_DISCRETE_2.2R_2.2R
SS1-SS8 = SPACER
SW1-SW3 = SW_TH3P
U1 U2 U26 = TP6327GS6
U3 U12 U13 U20 U24 U25 U31 U32 = LPW5209AB5F
U4 = IRM-V838M3-C/TR1
U5 = HYM8563S
U6 = LDO-3P
U7 U8 = RTL8211F
U9 = ES8388
U10 U38 = NS4110B
U11 = FUSB302BMPX
U14-U18 = RCLAMP0524P
U19 = FE2.1-CQFP48A
U22 = RTL8723
U27 = NUP5120-D
U28 U29 = 74LVC1G125
U33 = MAX3232CSE
U34 U35 = TJA1057GT3_8P
U36 U37 = SIT3088E-8P
Y1 = CRYSTAL_2P
Y2-Y4 = CRYSTAL_4P

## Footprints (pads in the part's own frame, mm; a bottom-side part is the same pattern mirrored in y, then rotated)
3215
  rect 1.4x1.2 smd: 1(-1.001,0) 2(1.001,0)
3225
  rect 1.3x1 smd: 1(-1.15,-0.75) 2(1.15,-0.75) 3(1.15,0.75) 4(-1.15,0.75)
AS0B821-S55B-7H
  round 1.1 hole 1.1 unplated: (-41,0.25)
  round 1.6 hole 1.6 unplated: (41,0.25)
  rect 0.3x2 smd: 1(-40,-3.95) 2(-39.75,3.95) 3(-39.5,-3.95) 4(-39.25,3.95) 5(-39,-3.95) 6(-38.75,3.95) 7(-38.5,-3.95) 8(-38.25,3.95) 9(-38,-3.95) 10(-37.75,3.95) 11(-37.5,-3.95) 12(-37.25,3.95) 13(-37,-3.95) 14(-36.75,3.95) 15(-36.5,-3.95) 16(-36.25,3.95) 17(-36,-3.95) 18(-35.75,3.95) 19(-35.5,-3.95) 20(-35.25,3.95) 21(-35,-3.95) 22(-34.75,3.95) 23(-34.5,-3.95) 24(-34.25,3.95) 25(-34,-3.95) 26(-33.75,3.95) 27(-33.5,-3.95) 28(-33.25,3.95) 29(-33,-3.95) 30(-32.75,3.95) 31(-32.5,-3.95) 32(-32.25,3.95) 33(-32,-3.95) 34(-31.75,3.95) 35(-31.5,-3.95) 36(-31.25,3.95) 37(-31,-3.95) 38(-30.75,3.95) 39(-30.5,-3.95) 40(-30.25,3.95) 41(-30,-3.95) 42(-29.75,3.95) 43(-29.5,-3.95) 44(-29.25,3.95) 45(-29,-3.95) 46(-28.75,3.95) 47(-28.5,-3.95) 48(-28.25,3.95) 49(-28,-3.95) 50(-27.75,3.95) 51(-27.5,-3.95) 52(-27.25,3.95) 53(-27,-3.95) 54(-26.75,3.95) 55(-26.5,-3.95) 56(-26.25,3.95) 57(-26,-3.95) 58(-25.75,3.95) 59(-25.5,-3.95) 60(-25.25,3.95) 61(-25,-3.95) 62(-24.75,3.95) 63(-24.5,-3.95) 64(-24.25,3.95) 65(-24,-3.95) 66(-23.75,3.95) 67(-23.5,-3.95) 68(-23.25,3.95) 69(-23,-3.95) 70(-22.75,3.95) 71(-22.5,-3.95) 72(-22.25,3.95) 73(-22,-3.95) 74(-21.75,3.95) 75(-21.5,-3.95) 76(-21.25,3.95) 77(-21,-3.95) 78(-20.75,3.95) 79(-20.5,-3.95) 80(-20.25,3.95) 81(-20,-3.95) 82(-19.75,3.95) 83(-19.5,-3.95) 84(-19.25,3.95) 85(-19,-3.95) 86(-18.75,3.95) 87(-18.5,-3.95) 88(-18.25,3.95) 89(-18,-3.95) 90(-17.75,3.95) 91(-17.5,-3.95) 92(-17.25,3.95) 93(-17,-3.95) 94(-16.75,3.95) 95(-16.5,-3.95) 96(-16.25,3.95) 97(-16,-3.95) 98(-15.75,3.95) 99(-15.5,-3.95) 100(-15.25,3.95) 101(-15,-3.95) 102(-14.75,3.95) 103(-14.5,-3.95) 104(-14.25,3.95) 105(-14,-3.95) 106(-13.75,3.95) 107(-13.5,-3.95) 108(-13.25,3.95) 109(-13,-3.95) 110(-12.75,3.95) 111(-12.5,-3.95) 112(-12.25,3.95) 113(-12,-3.95) 114(-11.75,3.95) 115(-11.5,-3.95) 116(-11.25,3.95) 117(-11,-3.95) 118(-10.75,3.95) 119(-10.5,-3.95) 120(-10.25,3.95) 121(-10,-3.95) 122(-9.75,3.95) 123(-9.5,-3.95) 124(-9.25,3.95) 125(-9,-3.95) 126(-8.75,3.95) 127(-8.5,-3.95) 128(-8.25,3.95) 129(-8,-3.95) 130(-7.75,3.95) 131(-7.5,-3.95) 132(-7.25,3.95) 133(-7,-3.95) 134(-6.75,3.95) 135(-6.5,-3.95) 136(-6.25,3.95) 137(-6,-3.95) 138(-5.75,3.95) 139(-5.5,-3.95) 140(-5.25,3.95) 141(-5,-3.95) 142(-4.75,3.95) 143(-4.5,-3.95) 144(-4.25,3.95) 145(-4,-3.95) 146(-3.75,3.95) 147(-3.5,-3.95) 148(-3.25,3.95) 149(-3,-3.95) 150(-2.75,3.95) 151(-2.5,-3.95) 152(-2.25,3.95) 153(-2,-3.95) 154(-1.75,3.95) 155(-1.5,-3.95) 156(-1.25,3.95) 157(-1,-3.95) 158(-0.75,3.95) 159(-0.5,-3.95) 160(-0.25,3.95) 161(0,-3.95) 162(0.25,3.95) 163(0.5,-3.95) 164(0.75,3.95) 165(1,-3.95) 166(3.25,3.95) 167(3,-3.95) 168(3.75,3.95) 169(3.5,-3.95) 170(4.25,3.95) 171(4,-3.95) 172(4.75,3.95) 173(4.5,-3.95) 174(5.25,3.95) 175(5,-3.95) 176(5.75,3.95) 177(5.5,-3.95) 178(6.25,3.95) 179(6,-3.95) 180(6.75,3.95) 181(6.5,-3.95) 182(7.25,3.95) 183(7,-3.95) 184(7.75,3.95) 185(7.5,-3.95) 186(8.25,3.95) 187(8,-3.95) 188(8.75,3.95) 189(8.5,-3.95) 190(9.25,3.95) 191(9,-3.95) 192(9.75,3.95) 193(9.5,-3.95) 194(10.25,3.95) 195(10,-3.95) 196(10.75,3.95) 197(10.5,-3.95) 198(11.25,3.95) 199(11,-3.95) 200(11.75,3.95) 201(11.5,-3.95) 202(12.25,3.95) 203(12,-3.95) 204(12.75,3.95) 205(12.5,-3.95) 206(13.25,3.95) 207(13,-3.95) 208(13.75,3.95) 209(13.5,-3.95) 210(14.25,3.95) 211(14,-3.95) 212(14.75,3.95) 213(14.5,-3.95) 214(15.25,3.95) 215(15,-3.95) 216(15.75,3.95) 217(15.5,-3.95) 218(16.25,3.95) 219(16,-3.95) 220(16.75,3.95) 221(16.5,-3.95) 222(17.25,3.95) 223(17,-3.95) 224(17.75,3.95) 225(17.5,-3.95) 226(18.25,3.95) 227(18,-3.95) 228(18.75,3.95) 229(18.5,-3.95) 230(19.25,3.95) 231(19,-3.95) 232(19.75,3.95) 233(19.5,-3.95) 234(20.25,3.95) 235(20,-3.95) 236(20.75,3.95) 237(20.5,-3.95) 238(21.25,3.95) 239(21,-3.95) 240(21.75,3.95) 241(21.5,-3.95) 242(22.25,3.95) 243(22,-3.95) 244(22.75,3.95) 245(22.5,-3.95) 246(23.25,3.95) 247(23,-3.95) 248(23.75,3.95) 249(23.5,-3.95) 250(24.25,3.95) 251(24,-3.95) 252(24.75,3.95) 253(24.5,-3.95) 254(25.25,3.95) 255(25,-3.95) 256(25.75,3.95) 257(25.5,-3.95) 258(26.25,3.95) 259(26,-3.95) 260(26.75,3.95) 261(26.5,-3.95) 262(27.25,3.95) 263(27,-3.95) 264(27.75,3.95) 265(27.5,-3.95) 266(28.25,3.95) 267(28,-3.95) 268(28.75,3.95) 269(28.5,-3.95) 270(29.25,3.95) 271(29,-3.95) 272(29.75,3.95) 273(29.5,-3.95) 274(30.25,3.95) 275(30,-3.95) 276(30.75,3.95) 277(30.5,-3.95) 278(31.25,3.95) 279(31,-3.95) 280(31.75,3.95) 281(31.5,-3.95) 282(32.25,3.95) 283(32,-3.95) 284(32.75,3.95) 285(32.5,-3.95) 286(33.25,3.95) 287(33,-3.95) 288(33.75,3.95) 289(33.5,-3.95) 290(34.25,3.95) 291(34,-3.95) 292(34.75,3.95) 293(34.5,-3.95) 294(35.25,3.95) 295(35,-3.95) 296(35.75,3.95) 297(35.5,-3.95) 298(36.25,3.95) 299(36,-3.95) 300(36.75,3.95) 301(36.5,-3.95) 302(37.25,3.95) 303(37,-3.95) 304(37.75,3.95) 305(37.5,-3.95) 306(38.25,3.95) 307(38,-3.95) 308(38.75,3.95) 309(38.5,-3.95) 310(39.25,3.95) 311(39,-3.95) 312(39.75,3.95) 313(39.5,-3.95) 314(40,-3.95)
  rect 3x5.15 smd: 315(43.4,1) 316(-43.4,1)
AV7_6X14R50_TM
  round 1.2 hole 1.2 unplated: (0,3.5) (0,-3.5)
  oval 1.2x2 hole 0.75x1.5: 1(-2.3,3.2) 2(-2.3,0.1) 3(-2.3,-2.7) 4(2.3,-3.1) 6(2.3,2) 7(2.3,-0.8) 8(-2.3,-5)
C0402
  rect 0.599x0.599 smd: 1(-0.5,0) 2(0.5,0)
C0805
  rect 1.16x1.47 smd: 1(-0.89,0) 2(0.89,0)
C1206
  rect 1.2x1.9 smd: 1(-1.6,0) 2(1.6,0)
CASE-B_3528
  rect 1.2x2.4 smd: 1(-1.45,0) 2(1.45,0)
DB2ERC-3P81-4P
  rect 1.8x1.8 hole 1.2: 1(-5.715,0)
  round 1.8 hole 1.2: 2(-1.905,0) 3(1.905,0) 4(5.715,0)
DB2ERC-3P81-6P
  rect 1.8x1.8 hole 1.2: 1(-9.525,0)
  round 1.8 hole 1.2: 2(-5.715,0) 3(-1.905,0) 4(1.905,0) 5(5.715,0) 6(9.525,0)
DC_IN_TH_3P_10R1X11R6
  round 1.999 hole 1.999 unplated: (-1.699,-1.25)
  oval 2.4x1.001 hole 1.801x0.399: 1(-2.751,-4.9) 5(-2.751,4.9)
  oval 2.7x1.5 hole 1.7x0.5: 2(4.501,-1.25) 3(4.501,4.049) 4(4.501,-4.45)
EC6P3
  rect 1.001x1.999 smd: 1(0,2.8) 2(0,-2.8)
ES0402
  rect 0.599x0.599 smd: 1(-0.5,0) 2(0.5,0)
ESD0402
  rect 0.599x0.599 smd: 1(-0.5,0) 2(0.5,0)
F1812
  rect 1.78x3.3 smd: 1(-2.305,0) 2(2.305,0)
FPC-30P-0P5
  rect 0.3x1.3 smd: 1(-7.25,1.35) 2(-6.75,1.35) 3(-6.25,1.35) 4(-5.75,1.35) 5(-5.25,1.35) 6(-4.75,1.35) 7(-4.25,1.35) 8(-3.75,1.35) 9(-3.25,1.35) 10(-2.75,1.35) 11(-2.25,1.35) 12(-1.75,1.35) 13(-1.25,1.35) 14(-0.75,1.35) 15(-0.25,1.35) 16(0.25,1.35) 17(0.75,1.35) 18(1.25,1.35) 19(1.75,1.35) 20(2.25,1.35) 21(2.75,1.35) 22(3.25,1.35) 23(3.75,1.35) 24(4.25,1.35) 25(4.75,1.35) 26(5.25,1.35) 27(5.75,1.35) 28(6.25,1.35) 29(6.75,1.35) 30(7.25,1.35)
  rect 1.6x2 smd: 31(9.4,-1.35) 32(-9.4,-1.35)
FPC_24P_0P5
  rect 0.3x1.3 smd: 1(-5.75,-1.351) 2(-5.25,-1.351) 3(-4.75,-1.351) 4(-4.25,-1.351) 5(-3.75,-1.351) 6(-3.25,-1.351) 7(-2.75,-1.351) 8(-2.25,-1.351) 9(-1.75,-1.351) 10(-1.25,-1.351) 11(-0.75,-1.351) 12(-0.25,-1.351) 13(0.25,-1.351) 14(0.75,-1.351) 15(1.25,-1.351) 16(1.75,-1.351) 17(2.25,-1.351) 18(2.75,-1.351) 19(3.25,-1.351) 20(3.75,-1.351) 21(4.25,-1.351) 22(4.75,-1.351) 23(5.25,-1.351) 24(5.75,-1.351)
  rect 1.6x2 smd: 25(7.45,1.351) 26(-7.45,1.351)
GH1P25_TH_2P
  rect 0.9x0.9 hole 0.5: 1(-0.625,0)
  round 0.9 hole 0.5: 2(0.625,0)
HDMI-SMD
  round 1.999 hole 1.999 unplated: (-6.05,-2) (7.2,1.5)
  round 0.7 hole 0.55: 1(5.3,0.5) 2(4.731,-0.5) 3(4.145,0.5) 4(3.575,-0.5) 5(2.99,0.5) 6(2.419,-0.5) 7(1.835,0.5) 8(1.263,-0.5) 9(0.68,0.5) 10(0.107,-0.5) 11(-0.475,0.5) 12(-1.049,-0.5) 13(-1.63,0.5) 14(-2.205,-0.5) 15(-2.785,0.5) 16(-3.361,-0.5) 17(-3.94,0.5) 18(-4.517,-0.5) 19(-5.095,0.5)
  oval 3.2x1.4 hole 2.7x0.9: G1(-6.05,3.25) G2(3.45,3.25) G3(-2.95,-3.25) G4(6.05,-3.25)
HDR1X3-2R54-TM-VM
  rect 1.6x1.6 hole 1: 1(-2.54,0)
  round 1.6 hole 1: 2(0,0) 3(2.54,0)
HDR2X3-2R54-TM-VM
  rect 1.6x1.6 hole 1: 1(-2.54,-1.27)
  round 1.6 hole 1: 2(-2.54,1.27) 3(0,-1.27) 4(0,1.27) 5(2.54,-1.27) 6(2.54,1.27)
HDR2X9-2R54-TM-VM
  rect 1.6x1.6 hole 1: 1(-10.16,-1.27)
  round 1.6 hole 1: 2(-10.16,1.27) 3(-7.62,-1.27) 4(-7.62,1.27) 5(-5.08,-1.27) 6(-5.08,1.27) 7(-2.54,-1.27) 8(-2.54,1.27) 9(0,-1.27) 10(0,1.27) 11(2.54,-1.27) 12(2.54,1.27) 13(5.08,-1.27) 14(5.08,1.27) 15(7.62,-1.27) 16(7.62,1.27) 17(10.16,-1.27) 18(10.16,1.27)
HY911130A
  round 3.25 hole 3.25 unplated: (-5.715,0) (5.715,0)
  round 1.6 hole 1: 1(5.72,-8.89) 2(4.45,-6.35) 3(3.18,-8.89) 4(1.91,-6.35) 5(0.64,-8.89) 6(-0.63,-6.35) 7(-1.9,-8.89) 8(-3.17,-6.35) 9(-4.44,-8.89) 10(-5.71,-6.35)
  round 1.8 hole 1.2: 11(6.625,4.9) 12(4.085,4.9) 13(-4.085,4.9) 14(-6.625,4.9)
  round 2.43 hole 1.83: 15(7.745,-3.05) 16(-7.745,-3.05)
L0402
  rect 0.599x0.599 smd: 1(-0.5,0) 2(0.5,0)
L0603
  rect 0.8x0.8 smd: 1(-0.8,0) 2(0.8,0)
L2520
  rect 1.118x2.032 smd: 1(-0.959,0) 2(0.959,0)
L4520
  rect 1.4x2.3 smd: 1(-1.8,0) 2(1.8,0)
LED_HS_0602_UR
  rect 0.77x0.599 smd: 1(-0.815,0) 2(0.815,0)
LQFP48_0P5_7X7
  rect 1.2x0.25 smd: 1(-4.25,2.75) 2(-4.25,2.25) 3(-4.25,1.75) 4(-4.25,1.25) 5(-4.25,0.75) 6(-4.25,0.25) 7(-4.25,-0.25) 8(-4.25,-0.75) 9(-4.25,-1.25) 10(-4.25,-1.75) 11(-4.25,-2.25) 12(-4.25,-2.75) 25(4.25,-2.751) 26(4.25,-2.251) 27(4.25,-1.751) 28(4.25,-1.251) 29(4.25,-0.751) 30(4.25,-0.251) 31(4.25,0.249) 32(4.25,0.749) 33(4.25,1.249) 34(4.25,1.749) 35(4.25,2.249) 36(4.25,2.749)
  rect 0.25x1.2 smd: 13(-2.75,-4.25) 14(-2.25,-4.25) 15(-1.75,-4.25) 16(-1.25,-4.25) 17(-0.75,-4.25) 18(-0.25,-4.25) 19(0.25,-4.25) 20(0.75,-4.25) 21(1.25,-4.25) 22(1.75,-4.25) 23(2.25,-4.25) 24(2.75,-4.25) 37(2.75,4.25) 38(2.25,4.25) 39(1.75,4.25) 40(1.25,4.25) 41(0.75,4.25) 42(0.25,4.25) 43(-0.25,4.25) 44(-0.75,4.25) 45(-1.25,4.25) 46(-1.75,4.25) 47(-2.25,4.25) 48(-2.75,4.25)
MIC2-4R00-TM
  round 1.1 hole 0.7: 1(-0.7,0) 2(0.7,0)
MSOP-8
  rect 0.3x1 smd: 1(-0.975,-2.2) 2(-0.325,-2.2) 3(0.325,-2.2) 4(0.975,-2.2) 5(0.975,2.2) 6(0.325,2.2) 7(-0.325,2.2) 8(-0.975,2.2)
NANO_SIM
  round 0.9 hole 0.9 unplated: (-5,-5.49) (3.5,-5.49)
  rect 0.5x1.3 smd: 1(0.25,6.74) 2(-2.29,6.74) 3(-4.83,6.74) 4(2.47,6.74) 5(1.52,6.74) 6(-1.02,6.74) 7(-3.56,6.74)
  rect 1x2.1 smd: 8(-6.5,5.26) 9(6.5,5.26) 10(-6.5,-6.74) 11(6.5,-6.74)
NPTH_M3
  round 3.2 hole 3.2 unplated: (0,0)
PCIE_52P
  round 1.6 hole 1.6 unplated: (-12.5,0)
  round 1.1 hole 1.1 unplated: (12.5,0)
  rect 0.6x2 smd: 1(-11.8,-4.1) 2(-11.4,4.1) 3(-11,-4.1) 4(-10.6,4.1) 5(-10.2,-4.1) 6(-9.8,4.1) 7(-9.4,-4.1) 8(-9,4.1) 9(-8.6,-4.1) 10(-8.2,4.1) 11(-7.8,-4.1) 12(-7.4,4.1) 13(-7,-4.1) 14(-6.6,4.1) 15(-6.2,-4.1) 16(-5.8,4.1) 17(-2.2,-4.1) 18(-1.8,4.1) 19(-1.4,-4.1) 20(-1,4.1) 21(-0.6,-4.1) 22(-0.2,4.1) 23(0.2,-4.1) 24(0.6,4.1) 25(1,-4.1) 26(1.4,4.1) 27(1.8,-4.1) 28(2.2,4.1) 29(2.6,-4.1) 30(3,4.1) 31(3.4,-4.1) 32(3.8,4.1) 33(4.2,-4.1) 34(4.6,4.1) 35(5,-4.1) 36(5.4,4.1) 37(5.8,-4.1) 38(6.2,4.1) 39(6.6,-4.1) 40(7,4.1) 41(7.4,-4.1) 42(7.8,4.1) 43(8.2,-4.1) 44(8.6,4.1) 45(9,-4.1) 46(9.4,4.1) 47(9.8,-4.1) 48(10.2,4.1) 49(10.6,-4.1) 50(11,4.1) 51(11.4,-4.1) 52(11.8,4.1)
  rect 2.15x2.6 smd: 53(14.65,-3.5) 54(-14.65,-3.5)
PH-1X2-2P0_L
  rect 1.1x1.1 hole 0.7: 1(-1,0)
  round 1.1 hole 0.7: 2(1,0)
PH-1X4-2P0
  rect 1.1x1.1 hole 0.7: 1(-3,0)
  round 1.1 hole 0.7: 2(-1,0) 3(1,0) 4(3,0)
PH-1X6-2P0
  rect 1.1x1.1 hole 0.7: 1(-5,0)
  round 1.1 hole 0.7: 2(-3,0) 3(-1,0) 4(1,0) 5(3,0) 6(5,0)
QFN28_0R45-4X4EP2R6X2R6
  oval 0.8x0.2 smd: 1(-2,1.35)
  rect 0.8x0.2 smd: 2(-2,0.9) 3(-2,0.45) 4(-2,0) 5(-2,-0.45) 6(-2,-0.9) 7(-2,-1.35) 15(2,-1.35) 16(2,-0.9) 17(2,-0.45) 18(2,0) 19(2,0.45) 20(2,0.9) 21(2,1.35)
  rect 0.2x0.8 smd: 8(-1.35,-2) 9(-0.9,-2) 10(-0.45,-2) 11(0,-2) 12(0.45,-2) 13(0.9,-2) 14(1.35,-2) 22(1.35,2) 23(0.9,2) 24(0.45,2) 25(0,2) 26(-0.45,2) 27(-0.9,2) 28(-1.35,2)
  rect 2x2 smd: 29(0,0)
QFP_40P_R
  oval 0.8x0.2 smd: 1(-2.5,1.8) 2(-2.5,1.4) 3(-2.5,1) 4(-2.5,0.6) 5(-2.5,0.2) 6(-2.5,-0.2) 7(-2.5,-0.6) 8(-2.5,-1) 9(-2.5,-1.4) 10(-2.5,-1.8) 21(2.5,-1.8) 22(2.5,-1.4) 23(2.5,-1) 24(2.5,-0.6) 25(2.5,-0.2) 26(2.5,0.2) 27(2.5,0.6) 28(2.5,1) 29(2.5,1.4) 30(2.5,1.8)
  oval 0.2x0.8 smd: 11(-1.8,-2.5) 12(-1.4,-2.5) 13(-1,-2.5) 14(-0.6,-2.5) 15(-0.2,-2.5) 16(0.2,-2.5) 17(0.6,-2.5) 18(1,-2.5) 19(1.4,-2.5) 20(1.8,-2.5) 31(1.8,2.5) 32(1.4,2.5) 33(1,2.5) 34(0.6,2.5) 35(0.2,2.5) 36(-0.2,2.5) 37(-0.6,2.5) 38(-1,2.5) 39(-1.4,2.5) 40(-1.8,2.5)
  rect 3x3 smd: 41(0,0)
R0201
  rect 0.35x0.35 smd: 1(-0.275,0) 2(0.275,0)
R0402
  rect 0.599x0.599 smd: 1(-0.5,0) 2(0.5,0)
R0603
  rect 0.8x0.8 smd: 1(-0.8,0) 2(0.8,0)
R0805
  rect 1.016x1.143 smd: 1(-1.016,0) 2(1.016,0)
RL-UM02WBS-8723BU
  oval 2x1 smd: 1(-6.3,3.97) 2(-6.3,1.97) 3(-6.3,-1.01) 4(-6.3,-3.17) 5(6.3,3.5) 6(6.3,0.97) 7(6.3,-2.53) 8(6.3,-5.33)
  oval 1x2 smd: 9(3.65,-6.9) 10(2.38,-6.9) 11(1.11,-6.9) 12(-0.16,-6.9) 13(-1.43,-6.9) 14(-2.7,-6.9)
SMD4-6R80X2R50
  rect 0.8x1.2 smd: 1(1.905,0) 2(0.635,0) 3(-0.635,0) 4(-1.905,0)
SMTSO-M2R5
  round 6.2 hole 4.22: 1(0,0)
SMTWE_M2
  round 5.3 hole 3: 1(0,0)
SOD323_T
  rect 0.8x0.8 smd: 1(-1.175,0) 2(1.175,0)
SOD523
  rect 0.6x0.7 smd: 1(-0.71,0) 2(0.71,0)
SOD-123
  rect 1.2x1.4 smd: 1(1.7,0) 2(-1.7,0)
SOIC16
  oval 2.032x0.61 smd: 1(-2.789,4.44) 2(-2.789,3.18) 3(-2.789,1.9) 4(-2.789,0.64) 5(-2.789,-0.64) 6(-2.789,-1.9) 7(-2.789,-3.18) 8(-2.789,-4.44) 9(2.789,-4.44) 10(2.789,-3.18) 11(2.789,-1.9) 12(2.789,-0.64) 13(2.789,0.64) 14(2.789,1.9) 15(2.789,3.18) 16(2.789,4.44)
SOP8
  oval 0.6x1.8 smd: 1(-1.905,-2.5) 2(-0.635,-2.5) 3(0.635,-2.5) 4(1.905,-2.5) 5(1.905,2.5) 6(0.635,2.5) 7(-0.635,2.5) 8(-1.905,2.5)
SOP-8-EP-2R5X3R4
  oval 0.4x1.4 smd: 1(-1.905,-2.6) 2(-0.635,-2.6) 3(0.635,-2.6) 4(1.905,-2.6) 5(1.905,2.6) 6(0.635,2.6) 7(-0.635,2.6) 8(-1.905,2.6)
  rect 3.3x2.4 smd: 9(0,0)
SOT23
  rect 0.914x0.914 smd: 1(-0.953,-0.991) 2(0.953,-0.991)
  rect 0.914x1.27 smd: 3(0,1.041)
SOT23-5
  rect 0.599x1.199 smd: 1(-0.95,-1.25) 2(0,-1.25) 3(0.95,-1.25) 4(0.95,1.25) 5(-0.95,1.25)
SOT23_6
  rect 0.7x0.9 smd: 1(-0.95,-1.2) 2(0,-1.2) 3(0.95,-1.2) 4(0.95,1.2) 5(0,1.2) 6(-0.95,1.2)
SOT563
  rect 0.3x0.45 smd: 1(-0.5,-0.675) 2(0,-0.675) 3(0.5,-0.675) 4(0.5,0.675) 5(0,0.675) 6(-0.5,0.675)
SOT-23-3
  rect 0.914x0.914 smd: 1(-0.953,-0.991) 2(0.953,-0.991)
  rect 0.914x1.27 smd: 3(0,1.041)
SOT-353
  rect 0.406x1.194 smd: 1(-0.65,-0.9) 2(0,-0.9) 3(0.65,-0.9) 4(0.65,0.9) 5(-0.65,0.9)
SW_TH3_4P5X4P5X6P5
  round 1.6 hole 1: 1(-1.55,0.975) 2(1.55,0.975) 3(0,-0.975)
TFCARD
  round 1 hole 1 unplated: (-4,0) (4,0)
  rect 0.7x1.6 smd: 1(3.2,10.5) 2(2.1,10.5) 3(1,10.5) 4(-0.1,10.5) 5(-1.2,10.5) 6(-2.3,10.5) 7(-3.4,10.5) 8(-4.5,10.5) 9(-5.6,10.5)
  rect 1.2x1.778 smd: 10(-6.8,10)
  rect 1.524x2.413 smd: 11(-6.8,0.4) 12(8.7,0.4)
  rect 1.778x1.778 smd: 13(7.8,10)
UFL-3
  rect 1.05x1.05 smd: 1(0,-1.5)
  rect 1.05x2.2 smd: 2(-1.5,0) 3(1.5,0)
unnamed#2
  round 1.016 smd: (0,0)
USB3D0-AF-18P
  round 1.1 hole 0.7: 1(-3.5,-1.501) 2(-1.001,-1.501) 3(1.001,-1.501) 4(3.5,-1.501) 5(4,0) 6(1.999,0) 7(0,0) 8(-1.999,0) 9(-4,0) 10(-3.5,1.699) 11(-1.001,1.699) 12(1.001,1.699) 13(3.5,1.699) 14(4,3.2) 15(1.999,3.2) 16(0,3.2) 17(-1.999,3.2) 18(-4,3.2)
  round 3.2 hole 2.4: 19(6.571,-3.5) 20(6.571,2.179) 21(-6.571,2.179) 22(-6.571,-3.5)
USB-A-D
  round 1.6 hole 1: 1(3.5,-6.5) 2(1,-6.5) 3(-1,-6.5) 4(-3.5,-6.5) 7(3.5,-3.5) 8(1,-3.5) 9(-1,-3.5) 10(-3.5,-3.5)
  round 2.6 hole 2: 5(-6.55,-6.5) 6(6.55,-6.5) 11(-6.55,-0.7) 12(6.55,-0.7)
